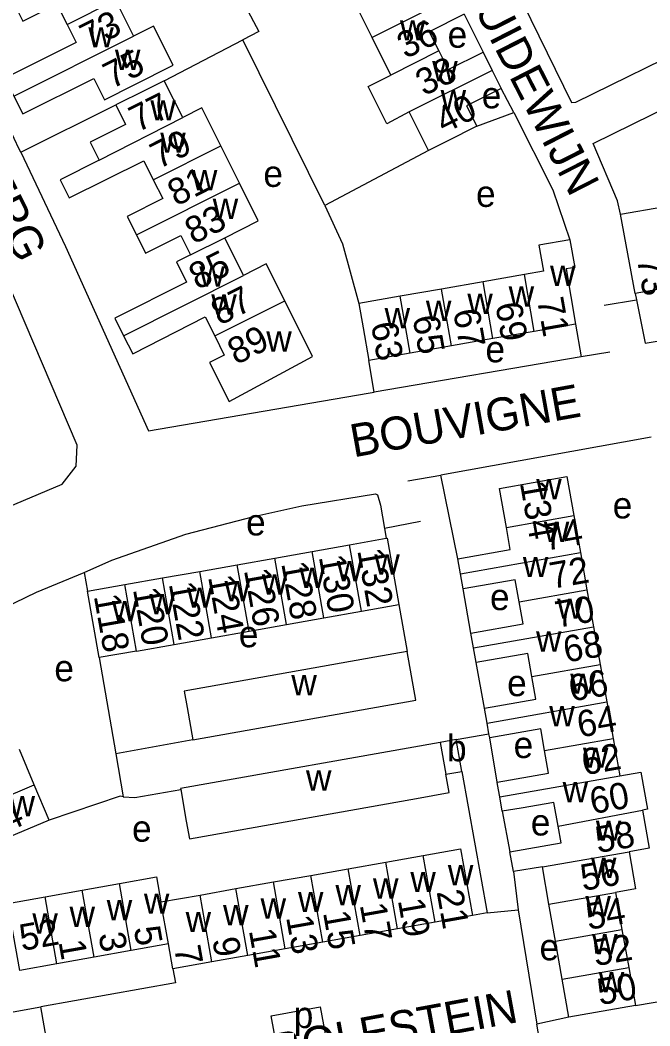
# Model space of a CAD drawing. Extents: x 157794 to 159375, y 380877 to 382306.
# Drawn here: x 158601.4 to 158697, y 381550.6 to 381703 of the extents above; entities that cross this region are included whole.
import ezdxf

# ---------------------------------------------------------------- set-up
doc = ezdxf.new("R2010")
doc.units = 0
for name, color, linetype in [('BLT_Basislijn', 7, 'Continuous'), ('BLT_Bebouwing', 7, 'Continuous'), ('BLT_Centroide', 7, 'Continuous'), ('BLT_Huisnummer', 7, 'Continuous'), ('BLT_Huisnummer_ tussenligend', 7, 'Continuous'), ('BLT_Onderverdeling_panden', 7, 'Continuous'), ('BLT_Straatnaam', 7, 'Continuous')]:
    doc.layers.add(name, color=color, linetype=linetype)

msp = doc.modelspace()

# ---------------------------------------------------------------- linework, layer by layer
at = {"layer": 'BLT_Basislijn'}
for p, q in [((158668.82, 381703.92), (158671.67, 381698.16)), ((158623.3, 381693.84), (158635.24, 381700.02)), ((158647.69, 381674.9), (158635.24, 381700.02)), ((158676.36, 381689.02), (158674.43, 381692.65)), ((158601.55, 381683), (158615.97, 381690.16)), ((158670.72, 381686.93), (158676.36, 381689.02)), ((158663.4, 381683.27), (158647.69, 381674.9)), ((158694.74, 381661.56), (158694.92, 381660.63)), ((158690.05, 381659.84), (158694.92, 381660.63)), ((158685.71, 381656.93), (158686.56, 381651.99)), ((158686.56, 381651.99), (158655.13, 381646.62)), ((158690.92, 381652.7), (158686.56, 381651.99)), ((158655.13, 381646.62), (158654.34, 381651.44)), ((158697.15, 381639.79), (158665.27, 381634.06)), ((158660.24, 381633.17), (158665.27, 381634.06)), ((158667.83, 381621.38), (158665.27, 381634.06)), ((158662.19, 381627.02), (158656.72, 381625.95)), ((158656.72, 381625.95), (158656.97, 381624.49)), ((158611.16, 381619.28), (158611.65, 381616.44)), ((158669.83, 381610.12), (158668.63, 381616.81)), ((158658.9, 381614.44), (158660.18, 381607.34)), ((158613.43, 381606.39), (158615.96, 381591.79)), ((158671.88, 381598.73), (158670.62, 381605.64)), ((158627.65, 381593.95), (158615.96, 381591.79)), ((158667.6, 381593.96), (158672.56, 381594.84)), ((158673.82, 381587.5), (158672.67, 381594.22)), ((158615.96, 381591.79), (158617.09, 381585.29)), ((158668.45, 381589.14), (158672.27, 381567.7)), ((158674.59, 381583.12), (158675.73, 381576.97)), ((158676.26, 381573.95), (158677.01, 381568.14)), ((158672.27, 381567.7), (158677.01, 381568.14)), ((158677.01, 381568.14), (158679.81, 381550.84)), ((158672.27, 381567.7), (158670.06, 381567.3)), ((158694.77, 381553.68), (158709.75, 381556.17)), ((158605.58, 381547.69), (158604.58, 381553.46)), ((158639.55, 381552.07), (158646.98, 381553.45)), ((158646.98, 381553.45), (158647.89, 381548.54)), ((158640.46, 381547.16), (158639.55, 381552.07)), ((158684.68, 381551.9), (158679.81, 381550.84))]:
    msp.add_line(p, q, dxfattribs=at)
for points in [[(158601.55, 381683), (158601.32, 381683.48), (158597.47, 381691.53), (158591.73, 381702.3), (158577.35, 381726.85), (158576.73, 381728.83)], [(158676.42, 381708.23), (158685.06, 381690.53), (158685.76, 381690.61), (158704.31, 381699.68), (158704.78, 381699.99), (158704.62, 381701.43), (158705.04, 381701.74), (158730.07, 381714.32)], [(158634.08, 381712.55), (158632.23, 381711.52), (158637.64, 381701.3), (158635.24, 381700.02)], [(158692.52, 381673.59), (158692.06, 381675.65), (158688.35, 381684.3), (158712.13, 381695.99), (158712.48, 381697.86), (158716.99, 381700.06)], [(158582.06, 381621.8), (158607.83, 381632.7), (158609.96, 381635.4), (158610.12, 381638.58), (158599.56, 381663.26), (158583.55, 381694.68)], [(158676.36, 381689.02), (158682.27, 381677.3), (158684.84, 381669.74)], [(158601.55, 381683), (158608.33, 381668.72), (158620.94, 381640.77), (158654.25, 381646.47), (158655.13, 381646.62)], [(158647.69, 381674.9), (158650.37, 381669.13), (158652.84, 381660.06)], [(158694.92, 381660.63), (158696.24, 381654.04), (158727.57, 381659.23)], [(158611.16, 381619.28), (158615.37, 381621.18), (158626.6, 381625.12), (158636.9, 381627.8), (158644.19, 381629.39), (158655.35, 381631.22), (158655.67, 381631.06), (158656.11, 381629.5), (158656.72, 381625.95)], [(158594.52, 381608.44), (158593.57, 381610.49), (158593.83, 381610.9), (158597.33, 381613.11), (158603.95, 381616.3), (158611.16, 381619.28)], [(158617.09, 381585.29), (158618.87, 381585.17), (158625.8, 381586.39)], [(158617.09, 381585.29), (158616.6, 381585.41), (158605.87, 381581.77)], [(158596.08, 381577.6), (158595.39, 381575.9), (158595.93, 381572.24), (158599.62, 381552.89), (158600.41, 381552.7), (158604.58, 381553.46)], [(158624.61, 381559.23), (158624.99, 381557.12), (158604.58, 381553.46)], [(158680.95, 381544.34), (158680.93, 381544.47), (158679.81, 381550.84)]]:
    msp.add_lwpolyline(points, dxfattribs=at)
at = {"layer": 'BLT_Bebouwing'}
for p, q in [((158615.91, 381706.04), (158618.64, 381700.58)), ((158654.83, 381700.38), (158652, 381706.05)), ((158671.67, 381698.16), (158673.05, 381695.4)), ((158673.05, 381695.4), (158674.43, 381692.65)), ((158626.11, 381688.24), (158623.3, 381693.84)), ((158663.4, 381683.27), (158660.48, 381689.11)), ((158634.71, 381678.29), (158631.87, 381683.96)), ((158692.52, 381673.59), (158698.94, 381674.74)), ((158694.74, 381661.56), (158692.52, 381673.59)), ((158635.35, 381664.32), (158632.49, 381670.03)), ((158677.93, 381664.45), (158671.66, 381663.35)), ((158671.66, 381663.35), (158665.38, 381662.26)), ((158701.02, 381662.7), (158694.74, 381661.56)), ((158659.11, 381661.16), (158652.84, 381660.06)), ((158665.38, 381662.26), (158659.11, 381661.16)), ((158685.71, 381656.93), (158679.44, 381655.84)), ((158679.44, 381655.84), (158673.17, 381654.74)), ((158666.89, 381653.64), (158660.62, 381652.54)), ((158673.17, 381654.74), (158666.89, 381653.64)), ((158660.62, 381652.54), (158654.34, 381651.44)), ((158685.44, 381627.93), (158686.43, 381622.3)), ((158651.43, 381623.5), (158656.97, 381624.49)), ((158645.75, 381622.49), (158651.43, 381623.5)), ((158634.38, 381620.48), (158640.07, 381621.48)), ((158640.07, 381621.48), (158645.75, 381622.49)), ((158668.23, 381619.09), (158667.83, 381621.38)), ((158686.43, 381622.3), (158687.42, 381616.68)), ((158628.7, 381619.47), (158634.38, 381620.48)), ((158617.33, 381617.45), (158623.02, 381618.46)), ((158623.02, 381618.46), (158628.7, 381619.47)), ((158668.63, 381616.81), (158668.23, 381619.09)), ((158611.65, 381616.44), (158617.33, 381617.45)), ((158613.43, 381606.39), (158611.65, 381616.44)), ((158687.42, 381616.68), (158688.41, 381611.08)), ((158653.22, 381613.43), (158658.9, 381614.44)), ((158641.85, 381611.42), (158647.53, 381612.43)), ((158647.53, 381612.43), (158653.22, 381613.43)), ((158636.17, 381610.41), (158641.85, 381611.42)), ((158688.41, 381611.08), (158689.42, 381605.34)), ((158624.8, 381608.4), (158630.48, 381609.41)), ((158630.48, 381609.41), (158636.17, 381610.41)), ((158670.22, 381607.88), (158669.83, 381610.12)), ((158619.11, 381607.39), (158624.8, 381608.4)), ((158670.62, 381605.64), (158670.22, 381607.88)), ((158619.11, 381607.39), (158613.43, 381606.39)), ((158689.42, 381605.34), (158690.42, 381599.67)), ((158672.27, 381596.47), (158671.88, 381598.73)), ((158690.42, 381599.67), (158691.39, 381594.12)), ((158672.56, 381594.84), (158672.27, 381596.47)), ((158672.67, 381594.22), (158672.56, 381594.84)), ((158691.39, 381594.12), (158692.39, 381588.48)), ((158603.6, 381587.11), (158601.33, 381592.44)), ((158605.87, 381581.77), (158603.6, 381587.11)), ((158673.88, 381587.17), (158673.82, 381587.5)), ((158674.21, 381585.28), (158673.88, 381587.17)), ((158674.59, 381583.12), (158674.21, 381585.28)), ((158662.59, 381576.41), (158668.27, 381577.42)), ((158668.27, 381577.42), (158670.06, 381567.3)), ((158656.91, 381575.4), (158662.59, 381576.41)), ((158676.26, 381573.95), (158675.73, 381576.97)), ((158693.82, 381576.96), (158694.81, 381571.35)), ((158645.54, 381573.39), (158651.23, 381574.39)), ((158651.23, 381574.39), (158656.91, 381575.4)), ((158680.66, 381574.7), (158676.26, 381573.95)), ((158681.66, 381569.04), (158680.66, 381574.7)), ((158639.86, 381572.38), (158645.54, 381573.39)), ((158605.22, 381570.13), (158610.86, 381571.13)), ((158610.86, 381571.13), (158616.5, 381572.13)), ((158628.74, 381570.4), (158634.18, 381571.37)), ((158634.18, 381571.37), (158639.86, 381572.38)), ((158694.81, 381571.35), (158691.75, 381570.81)), ((158622.81, 381569.35), (158628.74, 381570.4)), ((158691.75, 381570.81), (158692.74, 381565.19)), ((158682.65, 381563.41), (158681.66, 381569.04)), ((158670.06, 381567.3), (158664.39, 381566.3)), ((158658.71, 381565.29), (158653.02, 381564.28)), ((158664.39, 381566.3), (158658.71, 381565.29)), ((158692.74, 381565.19), (158693.76, 381559.44)), ((158653.02, 381564.28), (158647.34, 381563.27)), ((158618.3, 381561.99), (158612.66, 381560.99)), ((158623.94, 381562.99), (158618.3, 381561.99)), ((158624.61, 381559.23), (158623.94, 381562.99)), ((158641.66, 381562.26), (158635.98, 381561.25)), ((158647.34, 381563.27), (158641.66, 381562.26)), ((158683.66, 381557.66), (158682.65, 381563.41)), ((158612.66, 381560.99), (158607.02, 381559.99)), ((158635.98, 381561.25), (158630.51, 381560.28)), ((158630.51, 381560.28), (158624.61, 381559.23)), ((158693.76, 381559.44), (158694.77, 381553.68)), ((158684.68, 381551.9), (158683.66, 381557.66)), ((158694.77, 381553.68), (158684.68, 381551.9))]:
    msp.add_line(p, q, dxfattribs=at)
for points in [[(158600.55, 381705.49), (158601.87, 381702.88), (158607.02, 381705.46), (158608.57, 381702.36)], [(158668.82, 381703.92), (158663.51, 381701.27), (158664.95, 381698.39)], [(158608.57, 381702.36), (158609.93, 381699.64), (158599.14, 381694.23), (158600.51, 381691.49)], [(158600.51, 381691.49), (158601.86, 381688.8), (158612.65, 381694.16), (158614.26, 381690.96), (158618.73, 381693.2), (158624.67, 381696.18), (158621.69, 381702.11), (158618.64, 381700.58)], [(158657.69, 381694.68), (158654.83, 381700.38)], [(158664.95, 381698.39), (158666.39, 381695.52), (158671.67, 381698.16)], [(158660.48, 381689.11), (158657.06, 381687.32), (158654.23, 381692.95), (158657.69, 381694.68)], [(158623.3, 381693.84), (158620.48, 381692.43), (158615.97, 381690.16)], [(158674.43, 381692.65), (158669.17, 381690.01), (158670.72, 381686.93)], [(158615.97, 381690.16), (158617.45, 381687.2), (158612.07, 381684.5), (158613.43, 381681.79)], [(158631.87, 381683.96), (158628.99, 381689.71), (158626.11, 381688.24)], [(158670.72, 381686.93), (158666.24, 381684.69), (158663.4, 381683.27)], [(158613.43, 381681.79), (158607.52, 381678.83), (158608.88, 381676.1), (158620.2, 381681.71), (158621.64, 381678.83)], [(158621.64, 381678.83), (158623.09, 381675.96), (158617.69, 381673.25), (158619.09, 381670.46)], [(158632.49, 381670.03), (158637.57, 381672.58), (158634.71, 381678.29)], [(158619.09, 381670.46), (158620.48, 381667.68), (158625.84, 381670.36), (158627.31, 381667.43)], [(158684.84, 381669.74), (158680.14, 381668.92), (158680.83, 381664.96), (158677.93, 381664.45)], [(158684.84, 381669.74), (158685.58, 381665.53), (158684.25, 381665.3), (158685.71, 381656.93)], [(158627.31, 381667.43), (158625.16, 381666.36), (158626.69, 381663.3), (158615.82, 381657.85), (158617.15, 381655.19)], [(158641.58, 381660.48), (158638.79, 381666.06), (158635.35, 381664.32)], [(158630.96, 381655.15), (158632.41, 381652.25), (158630.19, 381651.14), (158633.17, 381645.21), (158645.81, 381652.03), (158641.58, 381660.48)], [(158652.84, 381660.06), (158653.48, 381656.37), (158654.34, 381651.44)], [(158617.15, 381655.19), (158618.53, 381652.43), (158629.5, 381658.05), (158630.96, 381655.15)], [(158675.2, 381626.13), (158674.17, 381632.02), (158684.4, 381633.83), (158685.44, 381627.93)], [(158667.83, 381621.38), (158675.8, 381622.78), (158675.2, 381626.13)], [(158656.97, 381624.49), (158657.11, 381624.51), (158658.9, 381614.44)], [(158677.14, 381614.87), (158676.55, 381618.2), (158668.63, 381616.81)], [(158669.83, 381610.12), (158677.73, 381611.51), (158677.14, 381614.87)], [(158660.18, 381607.34), (158655.26, 381606.46), (158626.34, 381601.33), (158626.78, 381598.85), (158627.65, 381593.95)], [(158627.65, 381593.95), (158661.49, 381599.94), (158660.18, 381607.34)], [(158679.09, 381603.51), (158678.47, 381607.02), (158670.62, 381605.64)], [(158671.88, 381598.73), (158679.69, 381600.1), (158679.09, 381603.51)], [(158681.01, 381592.3), (158680.43, 381595.58), (158672.67, 381594.22)], [(158667.6, 381593.96), (158665.15, 381593.53)], [(158668.45, 381589.14), (158667.6, 381593.96)], [(158665.15, 381593.53), (158625.78, 381586.53), (158625.8, 381586.39)], [(158673.82, 381587.5), (158681.61, 381588.87), (158681.01, 381592.3)], [(158625.8, 381586.39), (158626.65, 381581.61), (158627.12, 381578.94), (158661.58, 381585.06), (158666.51, 381585.94), (158666.01, 381588.71)], [(158666.01, 381588.71), (158668.45, 381589.14)], [(158692.39, 381588.48), (158695.61, 381589.04), (158696.6, 381583.41), (158695.85, 381583.28)], [(158683.04, 381580.86), (158682.42, 381584.43), (158677.43, 381583.56), (158674.59, 381583.12)], [(158695.85, 381583.28), (158696.87, 381577.5), (158693.82, 381576.96)], [(158605.87, 381581.77), (158600.68, 381579.56), (158596.08, 381577.6)], [(158675.73, 381576.97), (158683.5, 381578.31), (158683.04, 381580.86)], [(158616.5, 381572.13), (158622.14, 381573.14), (158622.81, 381569.35)], [(158607.02, 381559.99), (158601.38, 381558.99), (158599.58, 381569.13), (158605.22, 381570.13)]]:
    msp.add_lwpolyline(points, dxfattribs=at)
at = {"layer": 'BLT_Onderverdeling_panden'}
for p, q in [((158608.57, 381702.36), (158615.91, 381706.04)), ((158667.43, 381706.69), (158654.83, 381700.38)), ((158600.51, 381691.49), (158618.64, 381700.58)), ((158664.95, 381698.39), (158657.69, 381694.68)), ((158673.05, 381695.4), (158660.48, 381689.11)), ((158613.43, 381681.79), (158626.11, 381688.24)), ((158621.64, 381678.83), (158631.87, 381683.96)), ((158619.09, 381670.46), (158634.71, 381678.29)), ((158627.31, 381667.43), (158632.49, 381670.03)), ((158617.15, 381655.19), (158635.35, 381664.32)), ((158679.44, 381655.84), (158677.93, 381664.45)), ((158673.17, 381654.74), (158671.66, 381663.35)), ((158660.62, 381652.54), (158659.11, 381661.16)), ((158666.89, 381653.64), (158665.38, 381662.26)), ((158630.96, 381655.15), (158641.58, 381660.48)), ((158675.2, 381626.13), (158685.44, 381627.93)), ((158653.22, 381613.43), (158651.43, 381623.5)), ((158641.85, 381611.42), (158640.07, 381621.48)), ((158647.53, 381612.43), (158645.75, 381622.49)), ((158668.23, 381619.09), (158686.43, 381622.3)), ((158636.17, 381610.41), (158634.38, 381620.48)), ((158624.8, 381608.4), (158623.02, 381618.46)), ((158630.48, 381609.41), (158628.7, 381619.47)), ((158619.11, 381607.39), (158617.33, 381617.45)), ((158677.14, 381614.87), (158687.42, 381616.68)), ((158670.22, 381607.88), (158688.41, 381611.08)), ((158679.09, 381603.51), (158689.42, 381605.34)), ((158672.27, 381596.47), (158690.42, 381599.67)), ((158681.01, 381592.3), (158691.39, 381594.12)), ((158665.15, 381593.53), (158666.01, 381588.71)), ((158674.21, 381585.28), (158692.39, 381588.48)), ((158593.8, 381582.94), (158603.6, 381587.11)), ((158683.04, 381580.86), (158695.85, 381583.28)), ((158664.39, 381566.3), (158662.59, 381576.41)), ((158680.66, 381574.7), (158693.82, 381576.96)), ((158653.02, 381564.28), (158651.23, 381574.39)), ((158658.71, 381565.29), (158656.91, 381575.4)), ((158647.34, 381563.27), (158645.54, 381573.39)), ((158612.66, 381560.99), (158610.86, 381571.13)), ((158618.3, 381561.99), (158616.5, 381572.13)), ((158635.98, 381561.25), (158634.18, 381571.37)), ((158641.66, 381562.26), (158639.86, 381572.38)), ((158607.02, 381559.99), (158605.22, 381570.13)), ((158630.51, 381560.28), (158628.74, 381570.4)), ((158681.66, 381569.04), (158691.75, 381570.81)), ((158623.94, 381562.99), (158622.81, 381569.35)), ((158682.65, 381563.41), (158692.74, 381565.19)), ((158683.66, 381557.66), (158693.76, 381559.44))]:
    msp.add_line(p, q, dxfattribs=at)

# ---------------------------------------------------------------- texts
at = {"layer": 'BLT_Centroide'}
for s, p in [('w', (158659.06, 381699.94)), ('w', (158611.79, 381698.88)), ('e', (158666.29, 381698.84)), ('w', (158615.83, 381695.47)), ('w', (158663.95, 381693.75)), ('w', (158665.23, 381689.34)), ('e', (158671.46, 381689.65)), ('w', (158621.2, 381687.81)), ('w', (158622.7, 381682.91)), ('e', (158638.34, 381677.74)), ('w', (158627.5, 381677.22)), ('e', (158670.6, 381674.71)), ('w', (158630.66, 381672.88)), ('w', (158628.63, 381662.62)), ('w', (158681.83, 381662.73)), ('w', (158675.55, 381659.59)), ('w', (158630.44, 381658.38)), ('w', (158669.28, 381658.5)), ('w', (158663, 381657.41)), ('w', (158656.73, 381656.31)), ('w', (158638.79, 381652.78)), ('e', (158672.03, 381651.15)), ('w', (158679.73, 381630.38)), ('e', (158691.33, 381627.49)), ('e', (158635.72, 381624.91)), ('w', (158680.88, 381623.91)), ('w', (158655.17, 381618.97)), ('w', (158677.7, 381618.59)), ('w', (158643.8, 381616.95)), ('w', (158649.48, 381617.97)), ('w', (158638.11, 381615.94)), ('w', (158626.75, 381613.94)), ('w', (158632.44, 381614.94)), ('w', (158621.06, 381612.94)), ('e', (158672.72, 381613.59)), ('w', (158682.9, 381612.28)), ('w', (158615.38, 381611.91)), ('e', (158634.62, 381607.96)), ('w', (158679.7, 381607.31)), ('e', (158606.63, 381602.8)), ('w', (158642.59, 381600.66)), ('e', (158675.32, 381600.55)), ('w', (158684.88, 381600.91)), ('w', (158681.71, 381595.97)), ('b', (158666.2, 381590.68)), ('e', (158676.3, 381591.17)), ('w', (158686.82, 381589.69)), ('w', (158644.81, 381586.22)), ('w', (158683.73, 381584.47)), ('w', (158599.84, 381582.34)), ('e', (158678.91, 381579.43)), ('e', (158618.42, 381578.49)), ('w', (158688.78, 381578.62)), ('w', (158688.04, 381573)), ('w', (158666.33, 381571.86)), ('w', (158654.97, 381569.84)), ('w', (158660.64, 381570.84)), ('w', (158649.28, 381568.84)), ('w', (158614.58, 381566.56)), ('w', (158620.22, 381567.56)), ('w', (158637.92, 381566.81)), ('w', (158643.59, 381567.81)), ('w', (158687.19, 381567.19)), ('w', (158608.94, 381565.56)), ('w', (158632.23, 381565.81)), ('w', (158603.3, 381564.56)), ('w', (158626.55, 381564.78)), ('e', (158680.23, 381560.51)), ('w', (158688.2, 381561.44)), ('w', (158689.22, 381555.66)), ('p', (158642.95, 381550.24))]:
    msp.add_text(s, height=4, dxfattribs=at).set_placement(p)
at = {"layer": 'BLT_Huisnummer'}
for s, rotation, p in [('73', 26.6313, (158611.82, 381698.44)), ('36', 26.4154, (158659.91, 381697.09)), ('77', 26.6313, (158619.27, 381685.96)), ('40', 26.4154, (158665.74, 381685.76)), ('81', 26.6313, (158625.12, 381674.74)), ('85', 26.6313, (158628.35, 381662.07)), ('73', 279.9257, (158694.99, 381666.86)), ('71', 279.9257, (158679.84, 381660.68)), ('67', 279.9257, (158667.12, 381658.95)), ('89', 26.6313, (158634.21, 381650.7)), ('63', 279.9257, (158654.65, 381656.99)), ('134', 279.996, (158677.25, 381632.86)), ('74', 9.9827, (158681.17, 381622.58)), ('132', 280.061, (158652.58, 381622.65)), ('126', 280.061, (158635.39, 381619.63)), ('122', 280.061, (158623.99, 381617.58)), ('118', 280.061, (158612.61, 381615.73)), ('70', 9.9733, (158682.96, 381610.9)), ('66', 9.9733, (158685.04, 381599.72)), ('62', 9.9733, (158686.99, 381588.53)), ('54', 23.0526, (158596.85, 381578.83)), ('58', 9.9733, (158689.07, 381576.75)), ('21', 280.0586, (158664.61, 381570.91)), ('54', 9.9733, (158687.65, 381565.11)), ('17', 280.0586, (158652.96, 381568.92)), ('52', 10.0591, (158601.71, 381561.92)), ('13', 280.0586, (158641.78, 381567.04)), ('5', 280.0586, (158618.66, 381565.4)), ('9', 280.0586, (158630.58, 381563.69)), ('1', 280.0586, (158607.26, 381563.32)), ('50', 9.9733, (158689.36, 381553.7))]:
    msp.add_text(s, height=4, rotation=rotation, dxfattribs=at).set_placement(p)
at = {"layer": 'BLT_Huisnummer_ tussenligend'}
for s, rotation, p in [('75', 26.6313, (158615.35, 381692.54)), ('38', 26.4154, (158662.71, 381691.45)), ('79', 26.6313, (158622.48, 381680.4)), ('83', 26.6313, (158627.74, 381668.98)), ('87', 26.6313, (158631.71, 381656.67)), ('69', 279.9257, (158673.52, 381659.95)), ('65', 279.9257, (158660.96, 381657.99)), ('130', 280.061, (158646.74, 381621.68)), ('72', 9.9733, (158682.13, 381616.8)), ('128', 280.061, (158641.05, 381620.66)), ('124', 280.061, (158629.95, 381618.63)), ('120', 280.061, (158618.55, 381616.74)), ('68', 9.9733, (158684.21, 381605.62)), ('64', 9.9733, (158686.3, 381594.26)), ('60', 9.9733, (158688.22, 381582.65)), ('56', 9.9733, (158686.81, 381571.01)), ('19', 280.0586, (158658.73, 381569.61)), ('15', 280.0586, (158647.38, 381567.74)), ('11', 280.0586, (158636.13, 381565.04)), ('3', 280.0586, (158613.31, 381564.46)), ('52', 9.9733, (158688.7, 381559.61)), ('7', 280.0586, (158624.79, 381562.44))]:
    msp.add_text(s, height=4, rotation=rotation, dxfattribs=at).set_placement(p)
at = {"layer": 'BLT_Straatnaam'}
for s, rotation, p in [('ZUIDEWIJN', 297.0943, (158668.45, 381708.42)), ('RUWENBERG', 296.6337, (158581.47, 381705.46)), ('BOUVIGNE', 10.1849, (158652.01, 381636.73)), ('BOLESTEIN', 10.4764, (158640.3, 381544.35))]:
    msp.add_text(s, height=5, rotation=rotation, dxfattribs=at).set_placement(p)

doc.saveas('drawing.dxf')
